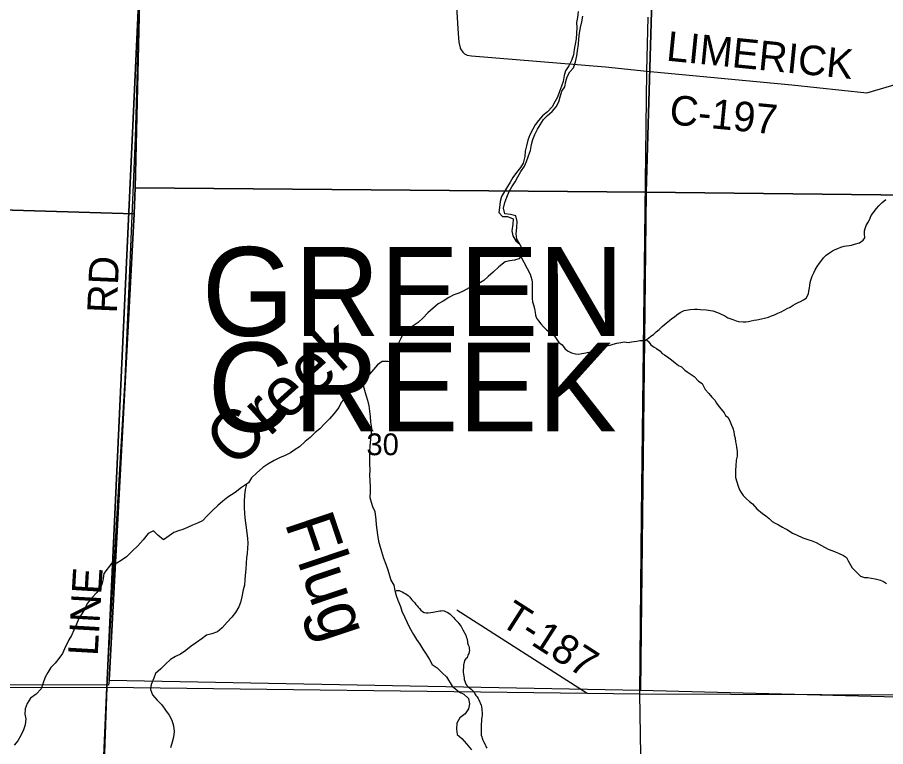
# Model space of a CAD drawing. Extents: x 1588073 to 2013523, y 1090242 to 1357120.
# Drawn here: x 1810221 to 1819023, y 1191598 to 1198993 of the extents above; entities that cross this region are included whole.
import ezdxf

# ---------------------------------------------------------------- set-up
doc = ezdxf.new("R2010")
doc.units = 0
for name, color, linetype in [('GM_X_County_Road', 7, 'Continuous'), ('GM_X_County_Road_Text', 7, 'Continuous'), ('GM_X_Minor_River', 7, 'Continuous'), ('GM_X_Minor_River_Text', 7, 'Continuous'), ('GM_X_Section', 7, 'Continuous'), ('GM_X_Section_Text', 7, 'Continuous'), ('GM_X_State_Route', 7, 'Continuous'), ('GM_X_Township', 7, 'Continuous'), ('GM_X_Township_Road', 7, 'Continuous'), ('GM_X_Township_Road_Text', 7, 'Continuous'), ('GM_X_Township_Text', 7, 'Continuous')]:
    doc.layers.add(name, color=color, linetype=linetype)

msp = doc.modelspace()

# ---------------------------------------------------------------- linework, layer by layer
at = {"layer": 'GM_X_County_Road'}
for points in [[(1814595.3, 1199879.8), (1814641.2, 1199616.3), (1814687.5, 1198877.5), (1814692, 1198785.2), (1814695.3, 1198741), (1814708.4, 1198684.6), (1814712.2, 1198674.5), (1814735.8, 1198640.1), (1814755, 1198624.9), (1814781.4, 1198609.2), (1814823.4, 1198602.5), (1816184.6, 1198490.4), (1816603.3, 1198446.4)], [(1816603.3, 1198446.4), (1818071.9, 1198309.6), (1818832.3, 1198227.2), (1819223, 1198343.2), (1820597, 1198772.5), (1821964.9, 1199197.8), (1823340.6, 1199611), (1823868.1, 1199755), (1824618.1, 1199777), (1825942.7, 1199751.8), (1827244.1, 1199779.1)], [(1811128.7, 1192201.7), (1811315, 1195321.6), (1811420.5, 1197772.8), (1811472.6, 1199649.3)], [(1800178.6, 1192224.6), (1801709.7, 1192206.2), (1803349.4, 1192206), (1804221.4, 1192206.1), (1805907.1, 1192205.2), (1808599, 1192198.2), (1811128.7, 1192201.7)], [(1811013.7, 1189578.6), (1811128.7, 1192201.7)], [(1811128.7, 1192201.7), (1815998.6, 1192141.5), (1816530.9, 1192135)], [(1816530.9, 1192135), (1819299.6, 1192124.1)]]:
    msp.add_lwpolyline(points, dxfattribs=at)
at = {"layer": 'GM_X_Minor_River'}
for points in [[(1815907.3, 1199054), (1815897.7, 1198992.1), (1815890.3, 1198942.2), (1815892.9, 1198890), (1815889.4, 1198833.9), (1815885.8, 1198775.9), (1815874.3, 1198720.1), (1815866.8, 1198666.2), (1815857.4, 1198614.3), (1815837.8, 1198556.7), (1815810.4, 1198503.3), (1815776.9, 1198452.1), (1815765.6, 1198402.3), (1815754, 1198342.5), (1815736.7, 1198294.8), (1815717.2, 1198241.2), (1815695.7, 1198185.7), (1815670.3, 1198136.3), (1815642.9, 1198084.9), (1815593.5, 1198036.1), (1815544.4, 1197995.4), (1815503, 1197946.4), (1815471.8, 1197905.1), (1815446.6, 1197859.7), (1815415, 1197802.5), (1815397.5, 1197746.8), (1815383.9, 1197689), (1815368.4, 1197635.3), (1815365, 1197583.3), (1815349.2, 1197515.6), (1815319.9, 1197470.3), (1815280.6, 1197421.2), (1815245.1, 1197370.1), (1815217.8, 1197320.7), (1815188.6, 1197277.4), (1815159.2, 1197226.1), (1815127.8, 1197176.8), (1815116.4, 1197125), (1815108.8, 1197065.1), (1815103.4, 1197013.1), (1815140.3, 1196974), (1815190.4, 1196972.6), (1815245.8, 1196951), (1815242.3, 1196895), (1815234.5, 1196829.1), (1815243.2, 1196778.7), (1815275.8, 1196725.7), (1815315, 1196694.5)], [(1815315, 1196694.5), (1815284.3, 1196745.5), (1815277.8, 1196799.8), (1815285.5, 1196863.7), (1815287.1, 1196921.8), (1815272.6, 1196980.4), (1815221, 1196995.8), (1815161, 1196999.5), (1815148.6, 1197058), (1815164.2, 1197115.7), (1815181.7, 1197169.3), (1815207.3, 1197228.8), (1815234.5, 1197274.1), (1815266, 1197325.4), (1815295.4, 1197376.7), (1815324.9, 1197430), (1815360.4, 1197485.2), (1815383.6, 1197530.7), (1815403.2, 1197588.3), (1815422.7, 1197643.9), (1815434.4, 1197705.7), (1815445.8, 1197755.5), (1815465.2, 1197807.1), (1815492.6, 1197858.5), (1815519.9, 1197903.8), (1815555.3, 1197957), (1815596.5, 1197997.9), (1815641.6, 1198038.8), (1815682.9, 1198085.8), (1815710.4, 1198137.2), (1815723.7, 1198186.9), (1815739.3, 1198244.6), (1815772.5, 1198287.8), (1815782, 1198341.7), (1815795.3, 1198391.4), (1815822.7, 1198440.8), (1815859.8, 1198481.9), (1815877.5, 1198543.6), (1815891.1, 1198603.3), (1815900.6, 1198655.2), (1815908.3, 1198721.1), (1815911.8, 1198773.2), (1815919.4, 1198833.1), (1815929, 1198891), (1815942.5, 1198948.8), (1815954.1, 1199004.6)], [(1818258.8, 1196303.9), (1818265.1, 1196327.9), (1818277.6, 1196367.9), (1818296, 1196401.8), (1818308.4, 1196431.7), (1818328.8, 1196465.5), (1818353.2, 1196499.3), (1818375.6, 1196531.2), (1818393.9, 1196555), (1818420.2, 1196580.8), (1818452.6, 1196606.5), (1818482.8, 1196624.2), (1818511, 1196637.9), (1818537.2, 1196649.7), (1818567.4, 1196663.4), (1818601.5, 1196673.1), (1818627.6, 1196676.8), (1818651.7, 1196680.5), (1818675.7, 1196682.3), (1818705.9, 1196692), (1818758.1, 1196707.4), (1818794.5, 1196735.1), (1818812.8, 1196759), (1818809.3, 1196799.1), (1818809.6, 1196829.2), (1818813.9, 1196853.2), (1818826.2, 1196883.1), (1818844.6, 1196915), (1818858.9, 1196940.9), (1818875.4, 1196982.8), (1818930.3, 1197054.4), (1818952.7, 1197082.2), (1818987.1, 1197115.9), (1819025.5, 1197147.6)], [(1815315, 1196694.5), (1815335.7, 1196647.8), (1815326, 1196583.9), (1815323.4, 1196570), (1815305.1, 1196545.5)], [(1815323.4, 1196570), (1815419.9, 1196390.6), (1815427.6, 1196364.5), (1815437.3, 1196332.3), (1815441, 1196308.2), (1815439.4, 1196172), (1815441.1, 1196141.9), (1815444.7, 1196109.8), (1815452.4, 1196079.6), (1815462, 1196041.4), (1815469.5, 1196001.3), (1815475.2, 1195973.1), (1815482.9, 1195943), (1815502.6, 1195914.7), (1815526.3, 1195884.4), (1815554, 1195854.1), (1815583.7, 1195825.7), (1815607.5, 1195807.4), (1815633.4, 1195791.1), (1815663.1, 1195766.7), (1815682.8, 1195736.4), (1815710.4, 1195698), (1815742.2, 1195673.6), (1815769.8, 1195637.2), (1815799.6, 1195612.9), (1815837.4, 1195592.4), (1815879.3, 1195579.9), (1815913.3, 1195577.6), (1815943.5, 1195585.3), (1815983.6, 1195590.8), (1816027.8, 1195600.4), (1816063.9, 1195610), (1816092.1, 1195623.7), (1816120.3, 1195635.5), (1816148.4, 1195643.2), (1816192.7, 1195662.7), (1816230.8, 1195668.3), (1816261, 1195680), (1816299.1, 1195689.6), (1816337.3, 1195697.3), (1816373.4, 1195702.9), (1816413.4, 1195696.4), (1816445.5, 1195702.1), (1816473.6, 1195707.8), (1816501.7, 1195711.5), (1816531.8, 1195715.2), (1816563.8, 1195716.9), (1816589.9, 1195718.6), (1816618.2, 1195740.3), (1816642.4, 1195762.1), (1816668.7, 1195777.9), (1816697, 1195805.6), (1816727.3, 1195829.3), (1816757.7, 1195857.1), (1816798.1, 1195892.7), (1816830.5, 1195920.4), (1816854.7, 1195938.2), (1816881, 1195958), (1816905.2, 1195975.8), (1816941.6, 1195999.4), (1816981.9, 1196021), (1817042.1, 1196030.4), (1817086.2, 1196033.9), (1817114.2, 1196033.6), (1817146.2, 1196031.3), (1817202.2, 1196026.7), (1817272.2, 1196015.9), (1817318.1, 1195999.4), (1817342, 1195989.1), (1817393.8, 1195966.5), (1817421.6, 1195946.1), (1817475.5, 1195929.5), (1817507.4, 1195917.1), (1817531.4, 1195910.9), (1817579.4, 1195906.4), (1817605.4, 1195906.1), (1817633.5, 1195909.8), (1817659.6, 1195915.5), (1817689.7, 1195921.2), (1817715.8, 1195924.9), (1817766, 1195936.4), (1817794.1, 1195942.1), (1817834.3, 1195953.7), (1817866.5, 1195965.4), (1817896.6, 1195977.1), (1817928.9, 1195992.8), (1817963.1, 1196008.5), (1817999.4, 1196028.1), (1818025.5, 1196039.9), (1818053.7, 1196055.6), (1818086, 1196073.3), (1818110.2, 1196087.1), (1818136.4, 1196100.8), (1818160.5, 1196112.6), (1818190.8, 1196130.3), (1818217, 1196146), (1818239.5, 1196189.9), (1818245.9, 1196217.9), (1818252.2, 1196249.9), (1818254.5, 1196275.9), (1818258.8, 1196303.9)], [(1815305.1, 1196545.5), (1815259.3, 1196532.7), (1815213.1, 1196523.2), (1815165, 1196515.7), (1815102.3, 1196462.2), (1815043.6, 1196408.8), (1814995, 1196367.2), (1814948.5, 1196325.6), (1814900.1, 1196296.1), (1814853.9, 1196280.5), (1814741, 1196217.6), (1814694.7, 1196196.1), (1814644.4, 1196180.6), (1814596, 1196151), (1814537.5, 1196115.6), (1814487.2, 1196088.1), (1814382, 1195997), (1814333.4, 1195947.4), (1814282.7, 1195897.8), (1814214.1, 1195850.5), (1814167.8, 1195830.9), (1814129.2, 1195783.2), (1814108.7, 1195737.4), (1814086.1, 1195689.5), (1814073.5, 1195635.5), (1814072.3, 1195531.3), (1814021.8, 1195495.8), (1813975.8, 1195502.3), (1813919.8, 1195504.9), (1813871.3, 1195469.4), (1813832.7, 1195421.7), (1813792.1, 1195374), (1813749.4, 1195320.3), (1813700.9, 1195282.8), (1813644.4, 1195241.3), (1813591.8, 1195193.8), (1813555.2, 1195146.1), (1813504.5, 1195088.5), (1813479.9, 1195038.6), (1813429, 1194973.1), (1813384.4, 1194921.4), (1813335.8, 1194871.8), (1813287.1, 1194820.2), (1813238.6, 1194782.7), (1813188, 1194733.1), (1813139.4, 1194691.6), (1813082.8, 1194638.1), (1813036.4, 1194610.5), (1812989.9, 1194576.9), (1812937.6, 1194551.4), (1812877.2, 1194526), (1812822.8, 1194498.6), (1812760.3, 1194463.2), (1812707.9, 1194427.7), (1812645.1, 1194372.2), (1812594.5, 1194322.6), (1812563.9, 1194272.9), (1812493.3, 1194227.5), (1812428.6, 1194174.1), (1812356, 1194126.8), (1812303.4, 1194087.3), (1812252.9, 1194043.7), (1812198.2, 1193992.2), (1812147.5, 1193940.6)], [(1816597, 1195724.1), (1816615.8, 1195710.3), (1816643.4, 1195673.9), (1816675.2, 1195647.5), (1816699.1, 1195637.2), (1816734.9, 1195610.8), (1816758.6, 1195584.5), (1816782.5, 1195572.2), (1816824.2, 1195541.7), (1816852, 1195519.3), (1816887.7, 1195488.9), (1816923.4, 1195462.4), (1816953.3, 1195448.1), (1816987, 1195415.6), (1817010.8, 1195399.4), (1817040.6, 1195377), (1817082.4, 1195350.5), (1817125.9, 1195303.9), (1817161.7, 1195279.5), (1817193, 1195219), (1817230.6, 1195180.5), (1817260.3, 1195142.1), (1817290, 1195111.7), (1817307.6, 1195081.5), (1817335.3, 1195045.1), (1817355, 1195018.8), (1817384.6, 1194982.4), (1817400.3, 1194956.2), (1817424.2, 1194937.9), (1817439.9, 1194909.7), (1817461.3, 1194859.3), (1817473, 1194827.1), (1817484.6, 1194792.9), (1817488.2, 1194758.8), (1817495.9, 1194726.7), (1817499.4, 1194688.6), (1817507.1, 1194662.4), (1817510.9, 1194636.3), (1817516.4, 1194592.2), (1817517.8, 1194544), (1817509.3, 1194502), (1817504.7, 1194444), (1817502.2, 1194403.9), (1817499.9, 1194373.9), (1817501.3, 1194327.7), (1817514.9, 1194283.5), (1817528.4, 1194241.3), (1817540, 1194201.1), (1817559.7, 1194176.8), (1817577.4, 1194144.5), (1817611, 1194110.1), (1817642.8, 1194085.7), (1817672.5, 1194059.3), (1817716, 1194008.7), (1817773.6, 1193962), (1817807.3, 1193937.6), (1817843.1, 1193913.1), (1817872.8, 1193882.8), (1817902.6, 1193864.4), (1817936.5, 1193846), (1817976.3, 1193825.5), (1818000.2, 1193811.2), (1818024.1, 1193799), (1818077.7, 1193764.3), (1818117.6, 1193747.8), (1818183.3, 1193715.1), (1818243.2, 1193696.4), (1818267.1, 1193688.1), (1818317, 1193667.5), (1818372.7, 1193636.9), (1818440.4, 1193600.1), (1818486.2, 1193583.5), (1818510.2, 1193575.2), (1818546.1, 1193560.8), (1818595.9, 1193538.2), (1818625.7, 1193515.9), (1818643.3, 1193483.6), (1818657.1, 1193459.4), (1818682.6, 1193413.1), (1818712.3, 1193380.7), (1818744, 1193350.2), (1818767.7, 1193325.9), (1818809.6, 1193313.5), (1818843.7, 1193313.1), (1818915.6, 1193300.3), (1818943.6, 1193294), (1818969.5, 1193285.7), (1819001.4, 1193271.3), (1819031.2, 1193253)], [(1813732.9, 1195307.6), (1813721, 1195286.6), (1813732.5, 1195238.3), (1813753.7, 1195166), (1813771.1, 1195111.7), (1813782.5, 1195055.4), (1813791.9, 1195001.2), (1813799.2, 1194945), (1813802.6, 1194888.8), (1813809.9, 1194828.6), (1813809.4, 1194782.5), (1813802.6, 1194714.5), (1813795.8, 1194644.4), (1813791.2, 1194592.3), (1813790.4, 1194520.2), (1813791.8, 1194464), (1813793.1, 1194405.9), (1813792.4, 1194347.8), (1813795.9, 1194295.6), (1813799.1, 1194231.4), (1813798.6, 1194181.3), (1813795.9, 1194125.2), (1813807.4, 1194079), (1813822.9, 1194032.8), (1813846.4, 1193982.4), (1813855.4, 1193898.1), (1813858.8, 1193846), (1813864.3, 1193797.8), (1813871.7, 1193745.6), (1813883, 1193681.3), (1813894.5, 1193633.1), (1813911.8, 1193576.8), (1813933.1, 1193508.4), (1813956.4, 1193448), (1813977.8, 1193391.7), (1813993.2, 1193335.4), (1814008.7, 1193285.1), (1814036.2, 1193236.7), (1814047.6, 1193182.5), (1814061, 1193130.2), (1814078.5, 1193083.9), (1814103.8, 1193019.5), (1814119.3, 1192973.2), (1814150.6, 1192908.8), (1814172, 1192856.4), (1814195.5, 1192806.1), (1814236.7, 1192735.5), (1814268.2, 1192685), (1814299.7, 1192638.6), (1814331.2, 1192588.1), (1814364.7, 1192537.6), (1814398.1, 1192483.2), (1814427.6, 1192432.7), (1814475.2, 1192396.1), (1814526.7, 1192347.5), (1814572.3, 1192304.9), (1814629.3, 1192210.1), (1814702.7, 1192151.1), (1814748.6, 1192130.6), (1814794.1, 1192086), (1814803.5, 1192031.8), (1814793, 1191981.8), (1814760.3, 1191930), (1814705.8, 1191890.5), (1814677.1, 1191836.7), (1814672.4, 1191774.7), (1814679.9, 1191722.5), (1814725.4, 1191679.9), (1814774.9, 1191627.2), (1814826.3, 1191564.5)], [(1812545.2, 1194260.9), (1812531.1, 1194205.1), (1812524.4, 1194147), (1812521.7, 1194082.9), (1812521, 1194020.8), (1812522.3, 1193964.7), (1812527.8, 1193918.5), (1812535.3, 1193868.3), (1812540.8, 1193822.1), (1812548.1, 1193763.9), (1812553.5, 1193713.8), (1812556.9, 1193657.6), (1812554.4, 1193611.6), (1812549.8, 1193557.5), (1812545.2, 1193511.4), (1812540.6, 1193457.4), (1812535.9, 1193399.3), (1812531.2, 1193335.2), (1812528.7, 1193289.1), (1812522.1, 1193235.1), (1812511.5, 1193187.1), (1812496.7, 1193117.1), (1812482, 1193061.1), (1812467.5, 1193015.2), (1812432.8, 1192957.4), (1812394.2, 1192911.8), (1812349.6, 1192860.1), (1812298.9, 1192804.6), (1812250.3, 1192761), (1812194, 1192741.6), (1812139.8, 1192728.1), (1812093.3, 1192694.5), (1812038.8, 1192655), (1811984.3, 1192617.6), (1811927.7, 1192574.1), (1811875.2, 1192536.6), (1811822.9, 1192511.1), (1811772.5, 1192481.5), (1811721.9, 1192434), (1811677.3, 1192388.4), (1811622.7, 1192338.8), (1811604.1, 1192292.9), (1811579.3, 1192229.1), (1811570.8, 1192179.1), (1811590.2, 1192124.7), (1811637.6, 1192070.1), (1811687.1, 1192021.5), (1811722.6, 1191966.9), (1811760.1, 1191918.4), (1811787.5, 1191866), (1811804.9, 1191809.7), (1811812.3, 1191753.5), (1811803.6, 1191695.5), (1811791, 1191643.5), (1811772.3, 1191585.6)], [(1812147.5, 1193940.6), (1812096.9, 1193887.1), (1812046.5, 1193863.6), (1811998.2, 1193844.1), (1811945.9, 1193820.6), (1811899.6, 1193799), (1811853.4, 1193785.5), (1811807.1, 1193769.9), (1811760.7, 1193736.4), (1811702.2, 1193696.9), (1811646.6, 1193741.6), (1811601, 1193786.2), (1811546.7, 1193758.7), (1811495.9, 1193695.1), (1811443.1, 1193635.6), (1811386.4, 1193580.1), (1811327.7, 1193524.6), (1811275.2, 1193485.1), (1811228.8, 1193459.5), (1811176.7, 1193456.1), (1811099.4, 1193352.7), (1811090.9, 1193304.7), (1811080.3, 1193254.7), (1811063.8, 1193208.8), (1811023.1, 1193159.1), (1810980.5, 1193111.4), (1810929.8, 1193049.8), (1810907.2, 1193004), (1810874.5, 1192944.2), (1810845.9, 1192896.4), (1810819.2, 1192840.6), (1810792.5, 1192778.7), (1810769.9, 1192726.9), (1810743.3, 1192681.1), (1810698.2, 1192589.3), (1810677.7, 1192543.5), (1810643.1, 1192493.7), (1810604.5, 1192446), (1810561.9, 1192400.4), (1810529.3, 1192348.6), (1810504.7, 1192302.8), (1810482, 1192244.9), (1810463.3, 1192183), (1810410.6, 1192131.4), (1810354.1, 1192090), (1810321.4, 1192034.2), (1810298.8, 1191980.3), (1810298.2, 1191928.2), (1810307.7, 1191882), (1810300.9, 1191819.9), (1810284.3, 1191768), (1810257.7, 1191712.2), (1810225, 1191658.4), (1810188.4, 1191612.7)], [(1814060.5, 1193183), (1814092.5, 1193182.4), (1814106.3, 1193176.1), (1814122.2, 1193169.8), (1814140, 1193159.4), (1814153.8, 1193151.1), (1814167.6, 1193140.8), (1814183.3, 1193130.5), (1814197.1, 1193118.2), (1814210.7, 1193099.9), (1814220.4, 1193085.7), (1814236, 1193069.3), (1814251.7, 1193055), (1814261.4, 1193040.8), (1814273.1, 1193026.5), (1814282.8, 1193012.3), (1814298.5, 1192998), (1814312.2, 1192981.7), (1814327.9, 1192967.3), (1814343.7, 1192959), (1814363.6, 1192954.6), (1814385.6, 1192956.2), (1814413.6, 1192959.6), (1814433.7, 1192961.2), (1814453.7, 1192964.8), (1814485.9, 1192972.2), (1814503.9, 1192975.8), (1814517.9, 1192975.5), (1814533.9, 1192977.2), (1814547.9, 1192974.9), (1814561.7, 1192968.6), (1814579.6, 1192960.3), (1814595.4, 1192951.9), (1814609.2, 1192941.7), (1814626.8, 1192923.3), (1814642.4, 1192908.9), (1814660, 1192888.6), (1814673.7, 1192874.3), (1814687.4, 1192862), (1814697.1, 1192845.8), (1814710.8, 1192831.4), (1814718.5, 1192815.3), (1814730.1, 1192797), (1814737.8, 1192782.8), (1814766.6, 1192728.2), (1814772.3, 1192712), (1814776, 1192697.9), (1814779.6, 1192681.8), (1814783.3, 1192663.8), (1814785, 1192649.7), (1814792.6, 1192631.5), (1814796.3, 1192617.4), (1814802, 1192603.3), (1814801.7, 1192589.3), (1814803.4, 1192575.2), (1814801.1, 1192561.2), (1814796.7, 1192541.3), (1814788.4, 1192527.4), (1814779.8, 1192499.6), (1814765.7, 1192489.8), (1814753.3, 1192472.1), (1814748.9, 1192454.1), (1814744.3, 1192426.2), (1814743.7, 1192396.1), (1814741.4, 1192380.2), (1814740.8, 1192352.1), (1814744.4, 1192332), (1814746, 1192314), (1814749.6, 1192295.9), (1814751.3, 1192277.8), (1814757, 1192263.7), (1814768.3, 1192231.4), (1814778, 1192217.2), (1814791.7, 1192204.9), (1814805.5, 1192194.6), (1814821.2, 1192180.3), (1814850.5, 1192149.6), (1814860.2, 1192135.4), (1814869.8, 1192117.2), (1814883.5, 1192102.9), (1814893.2, 1192086.7), (1814898.9, 1192072.6), (1814921.7, 1192018), (1814929, 1191981.8), (1814930.6, 1191963.8), (1814932.2, 1191943.7), (1814931.5, 1191911.7), (1814929.2, 1191897.7), (1814926.9, 1191879.7), (1814926.2, 1191849.7), (1814923.9, 1191831.7), (1814923.6, 1191817.7), (1814921.8, 1191731.6), (1814923.5, 1191715.5), (1814929.1, 1191697.4), (1814932.8, 1191683.3), (1814940.4, 1191665.1), (1814946.1, 1191651), (1814965.3, 1191614.5), (1814969, 1191600.4), (1814980.7, 1191584.2)]]:
    msp.add_lwpolyline(points, dxfattribs=at)
at = {"layer": 'GM_X_Section'}
for points in [[(1816749.4, 1202487.5), (1816596.6, 1197221.5), (1811414, 1197263.7), (1811533.5, 1202333.7), (1811540.6, 1202509.8)], [(1822034.1, 1202452.7), (1821947.1, 1197160.2), (1816596.6, 1197221.5), (1816749.4, 1202487.5)], [(1811533.5, 1202333.7), (1811414, 1197263.7), (1811404.4, 1197001.6), (1805790.5, 1197170.5), (1805889.1, 1202440.7)], [(1816596.6, 1197221.5), (1816539.2, 1192169.2), (1811150.9, 1192270.7), (1811404.4, 1197001.6), (1811414, 1197263.7)], [(1821947.1, 1197160.2), (1821865.2, 1192030), (1816539.2, 1192169.2), (1816596.6, 1197221.5)], [(1811404.4, 1197001.6), (1811150.9, 1192270.7), (1811146.6, 1192222.7), (1805927.9, 1192229.1), (1805896.9, 1194648.5), (1805767.2, 1196330.2), (1805790.5, 1197170.5)]]:
    msp.add_lwpolyline(points, close=True, dxfattribs=at)
at = {"layer": 'GM_X_State_Route'}
msp.add_lwpolyline([(1816679.6, 1189791.6), (1816665.3, 1189853.4), (1816652.3, 1189904), (1816633.7, 1189980.6), (1816568.8, 1190248.2), (1816558.2, 1190481.2), (1816530.9, 1192135), (1816546.8, 1193942.6), (1816603.3, 1198446.4), (1816614.5, 1198995.3)], dxfattribs=at)
at = {"layer": 'GM_X_Township'}
for points in [[(1809425.1, 1217858.4), (1812123.4, 1217805.2), (1812026.1, 1215616.5), (1811813.3, 1210447.7), (1811805.7, 1210261.1), (1811615.1, 1205771.9), (1811529.4, 1202309.8), (1811481.8, 1199847.7), (1811472.6, 1199649.3), (1811128.7, 1192201.7), (1810941.7, 1186950.1), (1808199.1, 1186945.3)], [(1827562, 1186497.2), (1821834.9, 1186718.2), (1819168.2, 1186783.7), (1818870.8, 1186791.5), (1818179.8, 1186809.7), (1817700, 1186825.7), (1817077.3, 1186837.8), (1816630.6, 1186847.6), (1816004.5, 1186857.3), (1815460.3, 1186868.8), (1813327.6, 1186913.8), (1810941.7, 1186950.1), (1811128.7, 1192201.7), (1811472.6, 1199649.3)]]:
    msp.add_lwpolyline(points, dxfattribs=at)
at = {"layer": 'GM_X_Township_Road'}
msp.add_lwpolyline([(1814677.1, 1192986.8), (1815998.6, 1192141.5)], dxfattribs=at)

# ---------------------------------------------------------------- texts
at = {"layer": 'GM_X_County_Road_Text'}
for s, rotation, p in [('LIMERICK', 354.30338, (1816791.9, 1198555.7)), ('C-197', 354.48172, (1816822.7, 1197910.6)), ('RD', 87.53137, (1811228.6, 1195988.1)), ('LINE', 86.66973, (1811035.1, 1192513.9))]:
    msp.add_text(s, height=300, rotation=rotation, dxfattribs=at).set_placement(p)
at = {"layer": 'GM_X_Minor_River_Text'}
for s, height, rotation, p in [('Creek', 500.24, 41.98788, (1812414, 1194410.3)), ('Flug', 500.32, 288.54865, (1812927.5, 1193870.6))]:
    msp.add_text(s, height=height, rotation=rotation, dxfattribs=at).set_placement(p)
at = {"layer": 'GM_X_Section_Text'}
msp.add_text('30', height=221, rotation=0.00001, dxfattribs=at).set_placement((1813759.8, 1194553.4))
at = {"layer": 'GM_X_Township_Road_Text'}
msp.add_text('T-187', height=300, rotation=327.39545, dxfattribs=at).set_placement((1815098.6, 1192843))
at = {"layer": 'GM_X_Township_Text'}
for s, p in [('GREEN', (1812091.5, 1195763.8)), ('CREEK', (1812150.9, 1194795.3))]:
    msp.add_text(s, height=900, rotation=0.00001, dxfattribs=at).set_placement(p)

doc.saveas('drawing.dxf')
